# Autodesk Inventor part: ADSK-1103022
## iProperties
Shininess: 24.0
Length Units: 11272
Angle Units: 11279
Time Units: 11290
Mass Units: 11286
Length Display Precision: 4
Angle Display Precision: 2
Compacted: True
Created: 2000-03
Part Number: ADSK-1103022
Document SubType Name: Modeling
Description: UHAN SPRING #334-2
Mass: 0.0822308 g
Surface Area: 0.886522 cm^2
Volume: 0.0101771 cm^3
Density: 8.08 g/cm^3
Material: Stainless Steel
Density: 0.0
Volumn: 0.0
Area: 0.0
PropertySet Name: Model Information
Control State: 0
Master: False
Checked Out: False
Author: Autodesk, Inc.
